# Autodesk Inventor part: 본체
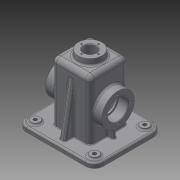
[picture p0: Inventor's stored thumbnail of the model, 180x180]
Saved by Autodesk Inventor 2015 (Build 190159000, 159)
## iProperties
Created: 2016-02
Part Number: 본체
Material: 일반
Document SubType Name: Modeling
Designer: Administrator
Density: 1 g/cm^3
Appearance: 기본값
Author: Administrator
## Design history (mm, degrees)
sketch "스케치1"
  geometry: L1 (-65, -57.5)-(65, -57.5); L2 (65, -57.5)-(65, 57.5); L3 (65, 57.5)-(-65, 57.5); L4 (-65, 57.5)-(-65, -57.5); L5 (-65, -57.5)-(65, 57.5); L6 (65, -57.5)-(-65, 57.5); 1 further point
  constraints: 12 end point, 2 midpoint, 2 parallel, 1 horizontal, 1 perpendicular
  dimensions: "d0" = 130 distance of L2.end L3.end; "d1" = 115 distance of L1.end L2.end
extrude "돌출1" new body sketch "스케치1" distance "d2" = 8; taper "d3" = 0 deg
sketch "스케치2"
  geometry: L1 (-32.5, 32.5)-(32.5, 32.5); L2 (32.5, 32.5)-(32.5, -32.5); L3 (32.5, -32.5)-(-32.5, -32.5); L4 (-32.5, -32.5)-(-32.5, 32.5); L5 (-32.5, 32.5)-(32.5, -32.5); L6 (32.5, 32.5)-(-32.5, -32.5); 1 further point
  constraints: 12 end point, 2 midpoint, 2 parallel, 1 horizontal, 1 perpendicular
  dimensions: "d4" = 65 distance of L1.start L1.end; "d5" = 65 distance of L1.end L2.end
extrude "돌출2" join sketch "스케치2" distance "d6" = 100; taper "d7" = 0 deg
sketch "스케치3"
  geometry: L1 (-114.421, 32.5)-(34.834, 32.5); L2 (8, -25)-(0, -25) reference; L3 (0, -25)-(0, 0) reference; L4 (0, 0)-(-100, 0) reference; L5 (-100, 0)-(-100, 65) reference; L6 (-100, 65)-(0, 65) reference; L7 (0, 65)-(0, 90) reference; L8 (0, 90)-(8, 90) reference; L9 (8, 90)-(8, -25) reference; L10 (0, 0)-(0, 65) reference; C1 r 27.5 at (-45, 32.5); 1 further point
  constraints: 2 end point, 1 centre point, 1 horizontal, 1 point on line
  dimensions: "d8" = 65 diameter of L4 L1; "d9" = 55 diameter of C1; "d10" = 53 distance from line of L9 C1.centre
extrude "돌출3" join sketch "스케치3" distance "d11" = 15; taper "d12" = 0 deg
sketch "스케치4"
  geometry: L1 (-65, 0)-(-65, 8) reference; L2 (-65, 8)-(-32.5, 8) reference; L3 (-32.5, 8)-(-32.5, 25.5) reference; L4 (-32.5, 25.5)-(-47.5, 25.5) reference; L5 (-47.5, 25.5)-(-47.5, 80.5) reference; L6 (-47.5, 80.5)-(-32.5, 80.5) reference; L7 (-32.5, 80.5)-(-32.5, 108) reference; L8 (-32.5, 108)-(32.5, 108) reference; L9 (32.5, 108)-(32.5, 80.5) reference; L10 (32.5, 80.5)-(47.5, 80.5) reference; L11 (47.5, 80.5)-(47.5, 25.5) reference; L12 (47.5, 25.5)-(32.5, 25.5) reference; L13 (32.5, 25.5)-(32.5, 8) reference; L14 (32.5, 8)-(65, 8) reference; L15 (65, 8)-(65, 0) reference; L16 (65, 0)-(-65, 0) reference; L17 (-27.5, 103)-(27.5, 103); L18 (27.5, 103)-(27.5, 0); L19 (27.5, 0)-(-27.5, 0); L20 (-27.5, 0)-(-27.5, 103); L21 (0, 108)-(0, 0)
  constraints: 10 end point, 2 parallel, 1 horizontal, 1 midpoint, 1 perpendicular, 1 point on line, 1 vertical
  dimensions: "d14" = 55 diameter of L20 L21; "d15" = 103 distance between parallel lines of L16 L17; "d16" = 55 diameter of L18 L21
extrude "돌출4" cut sketch "스케치4" stored distance "d17" = 55; taper "d18" = 0 deg
sketch "스케치5"
  geometry: L1 (-57.5, 0)-(-57.5, 8) reference; L2 (-57.5, 8)-(-32.5, 8) reference; L3 (-32.5, 8)-(-32.5, 108) reference; L4 (-32.5, 108)-(32.5, 108) reference; L5 (32.5, 108)-(32.5, 8) reference; L6 (32.5, 8)-(57.5, 8) reference; L7 (57.5, 8)-(57.5, 0) reference; L8 (57.5, 0)-(27.5, 0) reference; L9 (27.5, 0)-(27.5, 103) reference; L10 (27.5, 103)-(-27.5, 103) reference; L11 (-27.5, 103)-(-27.5, 0) reference; L12 (-27.5, 0)-(-57.5, 0) reference; L13 (-47.5, 8)-(-32.5, 93.069); L14 (-32.5, 8)-(-32.5, 108) reference; L15 (-32.5, 93.069)-(-32.5, 8); L16 (-57.5, 8)-(57.5, 8) reference; L17 (-32.5, 8)-(-47.5, 8); 1 further point
  constraints: 6 end point, 2 point on line, 1 collinear, 1 perpendicular
  dimensions: "d19" = 10 distance from line of L1 L13.start; "d20" = 100 deg angle of L13 L2
extrude "돌출5" join sketch "스케치5" stored distance "d21" = 10; taper "d22" = 0 deg
sketch "스케치6"
  geometry: L1 (-32.5, 25.5)-(-47.5, 25.5) reference; L2 (-47.5, 25.5)-(-47.5, 80.5) reference; L3 (-47.5, 80.5)-(-32.5, 80.5) reference; L4 (-32.5, 80.5)-(-32.5, 108) reference; L5 (-32.5, 108)-(32.5, 108) reference; L6 (32.5, 108)-(32.5, 80.5) reference; L7 (32.5, 80.5)-(47.5, 80.5) reference; L8 (47.5, 80.5)-(47.5, 25.5) reference; L9 (47.5, 25.5)-(32.5, 25.5) reference; L10 (32.5, 25.5)-(32.5, 8) reference; L11 (32.5, 8)-(65, 8) reference; L12 (65, 8)-(65, 0) reference; L13 (65, 0)-(27.5, 0) reference; L14 (27.5, 0)-(27.5, 103) reference; L15 (27.5, 103)-(-27.5, 103) reference; L16 (-27.5, 103)-(-27.5, 0) reference; L17 (-27.5, 0)-(-65, 0) reference; L18 (-65, 0)-(-65, 8) reference; L19 (-65, 8)-(-32.5, 8) reference; L20 (-32.5, 8)-(-32.5, 25.5) reference; L21 (65, 8)-(-65, 8) reference; L22 (42.5, 8)-(-42.5, 8); L23 (47.5, 25.5)-(32.5, 25.5) reference; L24 (-42.5, 8)-(-42.5, 30.849); L25 (-42.5, 30.849)-(42.5, 30.849); L26 (42.5, 30.849)-(42.5, 8); 1 further point
  constraints: 8 end point, 2 perpendicular, 2 point on line, 1 vertical
  dimensions: "d25" = 15 distance between parallel lines of L14 L26; "d26" = 15 distance between parallel lines of L16 L24; "d27" = 22.84869 distance between parallel lines of L21 L25
extrude "돌출6" join sketch "스케치6" stored distance "d28" = 6; taper "d29" = 0 deg
sketch "스케치7"
  geometry: L1 (-27.5, -27.5)-(27.5, -27.5) reference; L2 (27.5, -27.5)-(27.5, 27.5) reference; L3 (27.5, 27.5)-(-27.5, 27.5) reference; L4 (-27.5, 27.5)-(-27.5, -27.5) reference; L5 (65, 57.5)-(65, -57.5) reference; L6 (65, -57.5)-(-65, -57.5) reference; L7 (-65, -57.5)-(-65, 57.5) reference; L8 (-65, 57.5)-(65, 57.5) reference; L9 (-60, 52.5)-(60, 52.5); L10 (60, 52.5)-(60, -52.5); L11 (60, -52.5)-(-60, -52.5); L12 (-60, -52.5)-(-60, 52.5); L13 (-60, 52.5)-(60, -52.5); L14 (60, 52.5)-(-60, -52.5); 1 further point
  constraints: 12 end point, 2 midpoint, 2 parallel, 1 horizontal, 1 perpendicular
  dimensions: "d30" = 120 distance of L9.start L9.end; "d31" = 105 distance of L9.end L10.end
extrude "돌출7" join sketch "스케치7" distance "d32" = 2; taper "d33" = 0 deg
sketch "스케치8"
  geometry: L1 (-60, 52.5)-(60, 52.5) reference; L2 (60, 52.5)-(60, -52.5) reference; L3 (60, -52.5)-(-60, -52.5) reference; L4 (-60, -52.5)-(-60, 52.5) reference; L5 (27.5, -27.5)-(-27.5, -27.5); L6 (-27.5, -27.5)-(-27.5, 27.5); L7 (-27.5, 27.5)-(27.5, 27.5); L8 (27.5, 27.5)-(27.5, -27.5); L9 (27.5, -27.5)-(-27.5, 27.5); L10 (-27.5, -27.5)-(27.5, 27.5); 1 further point
  constraints: 12 end point, 2 midpoint, 2 parallel, 1 horizontal, 1 perpendicular
  dimensions: "d34" = 55 distance of L6.end L7.end; "d35" = 55 distance of L7.end L5.start
extrude "돌출8" cut sketch "스케치8" distance "d36" = 55; taper "d37" = 0 deg
fillet "모깎기1" dims "d38" = 10
fillet "모깎기2" dims "d39" = 15
sketch "스케치10"
  geometry: L1 (50, -57.5)-(-50, -57.5) reference; L2 (-65, -42.5)-(-65, 42.5) reference; L3 (-50, 57.5)-(50, 57.5) reference; L4 (65, 42.5)-(65, -42.5) reference; L5 (-42.5, -3)-(-42.5, 3) reference; L6 (-42.5, 3)-(-32.5, 3) reference; L7 (-32.5, 3)-(-32.5, 32.5) reference; L8 (-32.5, 32.5)-(-5, 32.5) reference; L9 (-5, 32.5)-(-5, 47.5) reference; L10 (-5, 47.5)-(5, 47.5) reference; L11 (5, 47.5)-(5, 32.5) reference; L12 (5, 32.5)-(32.5, 32.5) reference; L13 (32.5, 32.5)-(32.5, 3) reference; L14 (32.5, 3)-(42.5, 3) reference; L15 (42.5, 3)-(42.5, -3) reference; L16 (42.5, -3)-(32.5, -3) reference; L17 (32.5, -3)-(32.5, -32.5) reference; L18 (32.5, -32.5)-(5, -32.5) reference; L19 (5, -32.5)-(5, -47.5) reference; L20 (5, -47.5)-(-5, -47.5) reference; L21 (-5, -47.5)-(-5, -32.5) reference; L22 (-5, -32.5)-(-32.5, -32.5) reference; L23 (-32.5, -32.5)-(-32.5, -3) reference; L24 (-32.5, -3)-(-42.5, -3) reference; L25 (27.5, -27.5)-(27.5, 27.5) reference; L26 (27.5, 27.5)-(-27.5, 27.5) reference; L27 (-27.5, 27.5)-(-27.5, -27.5) reference; L28 (-27.5, -27.5)-(27.5, -27.5) reference; C1 r 7.5 at (50, -42.5); A1 r 15 centre (50, -42.5) between (50, -57.5) and (65, -42.5) reference; A2 r 15 centre (-50, -42.5) between (-65, -42.5) and (-50, -57.5) reference; A3 r 15 centre (-50, 42.5) between (-50, 57.5) and (-65, 42.5) reference; A4 r 15 centre (50, 42.5) between (65, 42.5) and (50, 57.5) reference; 1 further point
  constraints: 1 centre point, 1 coincident
  dimensions: "d40" = 15 diameter of C1
extrude "돌출9" join sketch "스케치10" distance "d41" = 3; taper "d42" = 0 deg
fillet "모깎기3" dims "d43" = 3
hole "구멍1" diameter "d46" = 6; stored, may be unused: countersink angle "d50" = 90 deg, drill point angle "d52" = 118 deg; dims "d44" = 10, "d45" = 10, "d47" = 6, "d48" = 4, "d49" = 2, "d51" = 8
node "작업 평면1"
sketch "스케치11"
  geometry: C1 r 20 at (0, 0); 1 further point
  constraints: 1 centre point, 1 coincident
  dimensions: "d60" = 40 diameter of C1
extrude "돌출10" join sketch "스케치11" stored distance "d61" = 3; taper "d62" = 0 deg
feature "면 기울기1" dims angle "d63" = 5 deg
fillet "모깎기4" dims "d64" = 8
fillet "모깎기6" dims "d66" = 8
sketch "스케치12"
  geometry: L1 (-45, 32.302)-(-45, -32.302) reference; L2 (-42, -35.429)-(-42, -40.842) reference; L3 (-42, -40.842)-(-55, -40.842) reference; L4 (-55, -40.842)-(-55, 40.842) reference; L5 (-55, 40.842)-(-42, 40.842) reference; L6 (-42, 40.842)-(-42, 35.429) reference; L7 (-53, -57.5)-(-53, -52.5) reference; L8 (-53, -52.5)-(-55, -52.5) reference; L9 (-55, -52.5)-(-55, -44.158) reference; L10 (-55, -44.158)-(-42, -44.158) reference; L11 (-42, -44.158)-(-42, -49.571) reference; L12 (-45, -52.698)-(-45, -57.5) reference; L13 (-45, -57.5)-(-53, -57.5) reference; L14 (-53, 52.5)-(-53, 57.5) reference; L15 (-53, 57.5)-(-45, 57.5) reference; L16 (-45, 57.5)-(-45, 52.698) reference; L17 (-42, 49.571)-(-42, 44.158) reference; L18 (-42, 44.158)-(-55, 44.158) reference; L19 (-55, 44.158)-(-55, 52.5) reference; L20 (-55, 52.5)-(-53, 52.5) reference; C1 r 27.5 at (0, 0) reference; C2 r 17.5 at (0, 0); 1 further point
  constraints: 1 centre point, 1 coincident, 4 other
  dimensions: "d67" = 35 diameter of C2
extrude "돌출11" cut sketch "스케치12" distance "d68" = 17; taper "d69" = 0 deg
sketch "스케치13"
  geometry: L1 (-55, -52.5)-(-55, 52.5) reference; L2 (-55, 52.5)-(-53, 52.5) reference; L3 (-53, 52.5)-(-53, 57.5) reference; L4 (-53, 57.5)-(-45, 57.5) reference; L5 (-45, 57.5)-(-45, 29.792) reference; L6 (-45, 29.792)-(47, 29.792) reference; L7 (52.292, 24.5)-(52.292, -24.5) reference; L8 (47, -29.792)-(-45, -29.792) reference; L9 (-45, -29.792)-(-45, -57.5) reference; L10 (-45, -57.5)-(-53, -57.5) reference; L11 (-53, -57.5)-(-53, -52.5) reference; L12 (-53, -52.5)-(-55, -52.5) reference; C1 r 17.5 at (0, 0) reference; C2 r 15 at (0, 0); A1 r 5.292 centre (47, 24.5) between (52.292, 24.5) and (47, 29.792) reference; A2 r 5.292 centre (47, -24.5) between (47, -29.792) and (52.292, -24.5) reference; 1 further point
  constraints: 1 centre point, 1 coincident
  dimensions: "d70" = 30 diameter of C2
extrude "돌출12" cut sketch "스케치13" stored distance "d71" = 17; taper "d72" = 0 deg
sketch "스케치14"
  geometry: C1 r 10.5 at (0, 0); 1 further point
  constraints: 1 centre point, 1 coincident
  dimensions: "d73" = 21 diameter of C1
extrude "돌출13" cut sketch "스케치14" stored distance "d74" = 17; taper "d75" = 0 deg
chamfer "모따기1" distance "d76" = 1; stored, may be unused: second distance "d77" = 2, angle "d78" = 45 deg
fillet "모깎기7" dims "d79" = 0.3
fillet "모깎기9" dims "d81" = 3
fillet "모깎기10" dims "d82" = 3
fillet "모깎기11" dims "d83" = 3
sketch "스케치16"
  geometry: L1 (-42, 44.158)-(-55, 44.158) reference; L2 (-55, 44.158)-(-55, 52.5) reference; L3 (-55, 52.5)-(-53, 52.5) reference; L4 (-53, 52.5)-(-53, 57.5) reference; L5 (-53, 57.5)-(-48, 57.5) reference; L6 (-45, 54.5)-(-45, 52.698) reference; L7 (-42, 49.571)-(-42, 44.158) reference; L8 (-42, -40.842)-(-55, -40.842) reference; L9 (-55, -40.842)-(-55, 40.842) reference; L10 (-55, 40.842)-(-42, 40.842) reference; L11 (-42, 40.842)-(-42, 35.429) reference; L12 (-45, 32.302)-(-45, -32.302) reference; L13 (-42, -35.429)-(-42, -40.842) reference; L14 (-53, -57.5)-(-53, -52.5) reference; L15 (-53, -52.5)-(-55, -52.5) reference; L16 (-55, -52.5)-(-55, -44.158) reference; L17 (-55, -44.158)-(-42, -44.158) reference; L18 (-42, -44.158)-(-42, -49.571) reference; L19 (-45, -52.698)-(-45, -54.5) reference; L20 (-48, -57.5)-(-53, -57.5) reference; C1 r 18.5 at (0, 0) reference; C2 r 27.5 at (0, 0) reference; A1 r 3 centre (-48, 54.5) between (-45, 54.5) and (-48, 57.5) reference; A2 r 3 centre (-48, -54.5) between (-48, -57.5) and (-45, -54.5) reference; 2 further points
  constraints: 4 other
  dimensions: "d84" = 0 vertical distance of C1.centre point (21, 0); "d85" = 21 distance of C2.centre point (21, 0)
hole "구멍2" sketch "스케치16" at (21, 0) diameter "d86" = 3.242; stored, may be unused: countersink angle "d90" = 90 deg, drill point angle "d92" = 118 deg; dims "d87" = 8, "d88" = 4, "d89" = 2, "d91" = 10
sketch "스케치17"
  geometry: C1 r 11.5 at (0, 0) reference; C2 r 20 at (0, 0) reference; 2 further points
  dimensions: "d96" = 0 horizontal distance of point (0, 0) point (0, -14.5); "d97" = 14.5 distance of point (0, 0) point (0, -14.5)
hole "구멍3" sketch "스케치17" at (0, -14.5) diameter "d98" = 2.459; stored, may be unused: countersink angle "d102" = 90 deg, drill point angle "d104" = 118 deg; dims "d99" = 7, "d100" = 4, "d101" = 2, "d103" = 9
node "작업 평면2"
fillet "모깎기12" dims "d112" = 3
fillet "모깎기15" dims "d115" = 3
fillet "모깎기17" dims "d117" = 3
fillet "모깎기18" dims "d118" = 3
fillet "모깎기19" dims "d119" = 3
fillet "모깎기20" dims "d120" = 1
fillet "모깎기21" dims "d121" = 3
sketch "스케치19"
  geometry: L1 (0, 57)-(-91, 57) reference; L2 (18, 44.5)-(18, 4.5) reference; 2 further points
  constraints: 1 other
  dimensions: "d122" = 26 distance from line of L2 point (-8, 24.5); "d123" = 32.5 distance from line of L1 point (-8, 24.5)
feature "엠보싱2" sketch "스케치19" dims "d124" = 0.5, "d125" = 0
node "솔리드1"
mirror "대칭1"
mirror "대칭2"
pattern_linear "직사각형 패턴1" dims "d55" = 85
mirror "대칭3"
pattern_circular "원형 패턴1" dims angle "d94" = 360 deg
mirror "대칭4"
pattern_circular "원형 패턴2" dims angle "d106" = 360 deg
mirror "대칭5"
node "절단 모서리 투영1"
node "절단 모서리 투영2"
node "절단 모서리 투영3"
node "절단 모서리 투영4"
node "절단 모서리 투영5"
node "절단 모서리 투영6"
node "절단 모서리 투영7"
node "절단 모서리 투영8"
node "절단 모서리 투영9"
node "절단 모서리 투영10"
node "절단 모서리 투영11"
